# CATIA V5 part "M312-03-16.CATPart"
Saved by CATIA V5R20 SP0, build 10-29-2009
Part number: M312-03-16
Revision: TUTTO
Definition: NON CONOSCIUTO
Nomenclature: M312-03-16
Source: Unknown
Bounding box of the stored display mesh (mm): x -20 to 20, y -20 to 20, z -24.8 to 111.2
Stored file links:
  C:\Users\Utente\Desktop\IO LAVORO\3D X SITO CF\X SITO\M312-03\M312-03-16.CATPart
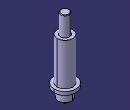
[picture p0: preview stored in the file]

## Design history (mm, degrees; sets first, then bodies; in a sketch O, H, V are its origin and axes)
Body1 "Sposta faccia1" (main body)
  Solid1: solid without history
